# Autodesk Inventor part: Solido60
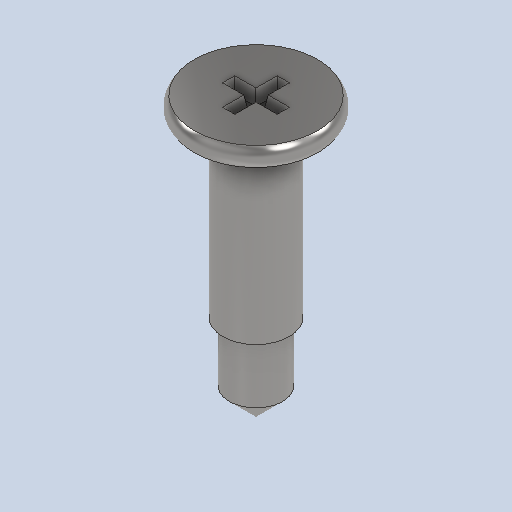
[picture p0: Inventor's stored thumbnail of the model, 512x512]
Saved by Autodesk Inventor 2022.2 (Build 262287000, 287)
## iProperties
Created: 2024-10
Part Number: Solido60
Material: Acciaio inossidabile
Document SubType Name: Modeling
Designer: 18907419
Density: 8 g/cm^3
Appearance: Default
Author: 18907419
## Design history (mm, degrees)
feature "Solido60"
node "Solido1"
